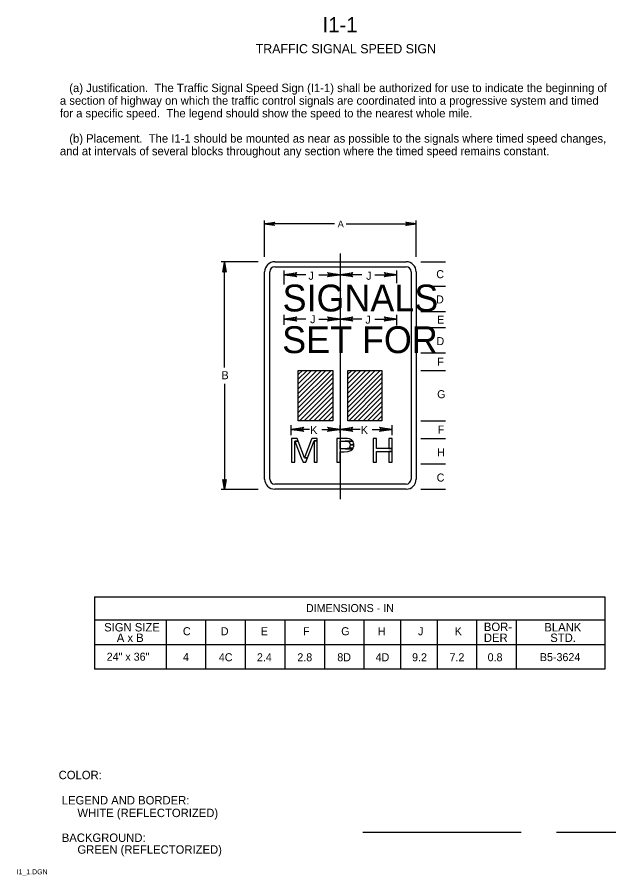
# Model space of a CAD drawing. Extents: x 0.013 to 0.191, y 0.004 to 0.259.
import ezdxf

# ---------------------------------------------------------------- set-up
doc = ezdxf.new("R2010")
doc.units = 0
for name, color, linetype in [('1', 7, 'Continuous'), ('2', 7, 'Continuous'), ('3', 7, 'Continuous')]:
    doc.layers.add(name, color=color, linetype=linetype)

# ---------------------------------------------------------------- blocks, each defined once
blk = doc.blocks.new('RARROW')
at = {"layer": '3'}
blk.add_lwpolyline([(-2.2695, 0.285), (-2.184875, 0.12075), (0, 0), (-2.2695, 0.285), (-2.38575, 0.384625), (0, 0), (-2.183125, -0.108), (-2.262875, -0.2705), (0, 0), (-2.38575, -0.379125), (-2.262875, -0.2705)], dxfattribs=at)

msp = doc.modelspace()

# ---------------------------------------------------------------- linework, layer by layer
at = {"layer": '1'}
for p, q in [((0.08625, 0.18768), (0.08625, 0.1985)), ((0.107, 0.1975), (0.08625, 0.1975)), ((0.1105, 0.1975), (0.13125, 0.1975)), ((0.13125, 0.18768), (0.13125, 0.1985)), ((0.10875, 0.18875), (0.10875, 0.11575)), ((0.08436, 0.18625), (0.07342, 0.18625)), ((0.07437, 0.15488), (0.07437, 0.18625)), ((0.13262, 0.18625), (0.14, 0.18625)), ((0.09212, 0.17955), (0.09212, 0.18365)), ((0.10875, 0.18415), (0.10875, 0.18115)), ((0.1255, 0.17992), (0.1255, 0.18365)), ((0.0985, 0.1824), (0.09212, 0.1824)), ((0.10237, 0.1824), (0.10875, 0.1824)), ((0.11512, 0.1824), (0.10875, 0.1824)), ((0.119, 0.1824), (0.1255, 0.1824)), ((0.13262, 0.179), (0.14, 0.179)), ((0.10875, 0.171), (0.10875, 0.168)), ((0.13262, 0.1715), (0.14, 0.1715)), ((0.09212, 0.1675), (0.09212, 0.1705)), ((0.0985, 0.16925), (0.09212, 0.16925)), ((0.10237, 0.16925), (0.10875, 0.16925)), ((0.11512, 0.16925), (0.10875, 0.16925)), ((0.119, 0.16925), (0.1255, 0.16925)), ((0.1255, 0.16737), (0.1255, 0.1705)), ((0.13262, 0.16675), (0.14, 0.16675)), ((0.13262, 0.15925), (0.14, 0.15925)), ((0.09625, 0.15275), (0.0975, 0.154)), ((0.09625, 0.15138), (0.09888, 0.154)), ((0.09625, 0.15), (0.10025, 0.154)), ((0.09625, 0.1485), (0.10175, 0.154)), ((0.09625, 0.14713), (0.10313, 0.154)), ((0.09625, 0.14575), (0.1045, 0.154)), ((0.09625, 0.14425), (0.106, 0.154)), ((0.09625, 0.14288), (0.1065, 0.15313)), ((0.111, 0.15288), (0.11213, 0.154)), ((0.111, 0.1515), (0.1135, 0.154)), ((0.111, 0.15013), (0.11488, 0.154)), ((0.111, 0.14863), (0.11638, 0.154)), ((0.111, 0.14725), (0.11775, 0.154)), ((0.111, 0.14588), (0.11913, 0.154)), ((0.111, 0.14438), (0.12062, 0.154)), ((0.111, 0.143), (0.12112, 0.15313)), ((0.13262, 0.154), (0.14, 0.154)), ((0.09625, 0.1415), (0.1065, 0.15175)), ((0.111, 0.14163), (0.12112, 0.15175)), ((0.07437, 0.15), (0.07437, 0.11863)), ((0.09625, 0.14012), (0.1065, 0.15038)), ((0.09663, 0.139), (0.1065, 0.14888)), ((0.111, 0.14025), (0.12112, 0.15038)), ((0.11125, 0.139), (0.12112, 0.14888)), ((0.098, 0.139), (0.1065, 0.1475)), ((0.09938, 0.139), (0.1065, 0.14613)), ((0.11263, 0.139), (0.12112, 0.1475)), ((0.114, 0.139), (0.12112, 0.14613)), ((0.10088, 0.139), (0.1065, 0.14463)), ((0.10225, 0.139), (0.1065, 0.14325)), ((0.1155, 0.139), (0.12112, 0.14463)), ((0.11688, 0.139), (0.12112, 0.14325)), ((0.10363, 0.139), (0.1065, 0.14188)), ((0.10512, 0.139), (0.1065, 0.14037)), ((0.11825, 0.139), (0.12112, 0.14188)), ((0.11975, 0.139), (0.12112, 0.14037)), ((0.09413, 0.13475), (0.09413, 0.13775)), ((0.10875, 0.1355), (0.10875, 0.13775)), ((0.12412, 0.13475), (0.12412, 0.13775)), ((0.13262, 0.139), (0.14, 0.139)), ((0.09963, 0.1365), (0.09413, 0.1365)), ((0.10325, 0.1365), (0.10875, 0.1365)), ((0.11463, 0.1365), (0.10875, 0.1365)), ((0.11825, 0.1365), (0.12412, 0.1365)), ((0.13262, 0.13375), (0.14, 0.13375)), ((0.13262, 0.12625), (0.14, 0.12625)), ((0.08438, 0.11865), (0.07343, 0.11865)), ((0.13262, 0.11875), (0.14, 0.11875)), ((0.11544, 0.01695), (0.16242, 0.01695)), ((0.17295, 0.01695), (0.19056, 0.01695))]:
    msp.add_line(p, q, dxfattribs=at)
for points in [[(0.09625, 0.154), (0.1065, 0.154), (0.1065, 0.139), (0.09625, 0.139)], [(0.111, 0.154), (0.12112, 0.154), (0.12112, 0.139), (0.111, 0.139)], [(0.09422, 0.12806), (0.09422, 0.12675), (0.09522, 0.12675), (0.09522, 0.12806), (0.09522, 0.13301), (0.09624, 0.13301), (0.09593, 0.13382), (0.09422, 0.13382), (0.09422, 0.13301)], [(0.09718, 0.12806), (0.0977, 0.12675), (0.09856, 0.12675), (0.09905, 0.12806), (0.09815, 0.12806), (0.09624, 0.13301), (0.09522, 0.13301)], [(0.1, 0.13307), (0.09815, 0.12806), (0.09905, 0.12806), (0.10095, 0.13307), (0.10193, 0.13307), (0.10193, 0.13382), (0.10027, 0.13382)], [(0.10095, 0.12806), (0.10095, 0.12675), (0.10193, 0.12675), (0.10193, 0.12806), (0.10193, 0.13307), (0.10095, 0.13307)], [(0.10774, 0.12986), (0.10774, 0.12675), (0.10874, 0.12675), (0.10874, 0.12986), (0.10986, 0.12986), (0.111, 0.12993), (0.11187, 0.13021), (0.11243, 0.13071), (0.11244, 0.13072), (0.10874, 0.13072), (0.10874, 0.13073), (0.10874, 0.13077), (0.10874, 0.13092), (0.10874, 0.13128), (0.10874, 0.13136), (0.10874, 0.13186), (0.10874, 0.13214), (0.10874, 0.13244), (0.10874, 0.1328), (0.10874, 0.1329), (0.10874, 0.13295), (0.10874, 0.133), (0.10874, 0.13301), (0.11245, 0.13301), (0.11207, 0.13342), (0.11148, 0.13369), (0.11087, 0.13379), (0.11035, 0.13382), (0.10774, 0.13382), (0.10774, 0.13379), (0.10774, 0.13369), (0.10774, 0.13342), (0.10774, 0.13301), (0.10774, 0.133), (0.10774, 0.13295), (0.10774, 0.1329), (0.10774, 0.1328), (0.10774, 0.13244), (0.10774, 0.13214), (0.10774, 0.13186), (0.10774, 0.13136), (0.10774, 0.13128), (0.10774, 0.13092), (0.10774, 0.13077), (0.10774, 0.13073), (0.10774, 0.13072), (0.10774, 0.13071), (0.10774, 0.13021), (0.10774, 0.12993)], [(0.11167, 0.13214), (0.11173, 0.13186), (0.11276, 0.13186), (0.11277, 0.13214), (0.11269, 0.13244), (0.11258, 0.1328), (0.11258, 0.1328), (0.11255, 0.1329), (0.1125, 0.13295), (0.11246, 0.133), (0.11245, 0.13301), (0.11018, 0.13301), (0.11045, 0.133), (0.11088, 0.13295), (0.11102, 0.1329), (0.1113, 0.1328), (0.11161, 0.13244)], [(0.1185, 0.12996), (0.1185, 0.12675), (0.11951, 0.12675), (0.11951, 0.12996), (0.12419, 0.12996), (0.12419, 0.1308), (0.11951, 0.1308), (0.11951, 0.13382), (0.1185, 0.13382), (0.1185, 0.1308)], [(0.12319, 0.13382), (0.12319, 0.1308), (0.12419, 0.1308), (0.12419, 0.13382)], [(0.11041, 0.13073), (0.11018, 0.13072), (0.11244, 0.13072), (0.11244, 0.13073), (0.11246, 0.13077), (0.11253, 0.13092), (0.11127, 0.13092), (0.11082, 0.13077)], [(0.11161, 0.13128), (0.11127, 0.13092), (0.11253, 0.13092), (0.11269, 0.13128), (0.11273, 0.13136), (0.11276, 0.13186), (0.11173, 0.13186), (0.11163, 0.13136)], [(0.12319, 0.12996), (0.12319, 0.12675), (0.12419, 0.12675), (0.12419, 0.12996)]]:
    msp.add_lwpolyline(points, close=True, dxfattribs=at)
at = {"layer": '3'}
for p, q in [((0.08929, 0.18625), (0.12829, 0.18625)), ((0.08929, 0.18475), (0.12829, 0.18475)), ((0.08629, 0.12175), (0.08629, 0.18325)), ((0.08779, 0.12175), (0.08779, 0.18325)), ((0.12979, 0.18325), (0.12979, 0.12175)), ((0.13129, 0.18325), (0.13129, 0.12175)), ((0.12829, 0.12025), (0.08929, 0.12025)), ((0.12829, 0.11875), (0.08929, 0.11875)), ((0.03577, 0.08675), (0.18727, 0.08675)), ((0.03577, 0.08675), (0.03577, 0.06525)), ((0.18727, 0.08675), (0.18727, 0.06525)), ((0.18727, 0.07988), (0.03577, 0.07988)), ((0.05706, 0.0799), (0.05706, 0.06527)), ((0.06877, 0.07988), (0.06877, 0.06525)), ((0.08052, 0.07988), (0.08052, 0.06525)), ((0.09227, 0.07988), (0.09227, 0.06525)), ((0.10402, 0.07988), (0.10402, 0.06525)), ((0.11577, 0.07988), (0.11577, 0.06525)), ((0.12664, 0.07988), (0.12664, 0.06525)), ((0.13752, 0.07988), (0.13752, 0.06525)), ((0.14919, 0.0799), (0.14919, 0.06527)), ((0.16094, 0.0799), (0.16094, 0.06527)), ((0.18727, 0.0725), (0.03577, 0.0725)), ((0.18727, 0.06525), (0.03577, 0.06525))]:
    msp.add_line(p, q, dxfattribs=at)
for centre, radius, start, end in [((0.08929, 0.18325), 0.003, 90, 180), ((0.12829, 0.18325), 0.003, 0, 90), ((0.08929, 0.18325), 0.0015, 90, 180), ((0.12829, 0.18325), 0.0015, 0, 90), ((0.08929, 0.12175), 0.003, 180, 270), ((0.08929, 0.12175), 0.0015, 180, 270), ((0.12829, 0.12175), 0.003, 270, 0), ((0.12829, 0.12175), 0.0015, 270, 0)]:
    msp.add_arc(centre, radius, start, end, dxfattribs=at)

# ---------------------------------------------------------------- block references
at = {"layer": '1'}
for p, xscale, yscale, rotation in [((0.08625, 0.1975), 0.0012574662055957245, 0.001309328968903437, 180), ((0.07437, 0.18613), 0.0012574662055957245, 0.001309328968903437, 90), ((0.09212, 0.1824), 0.0015718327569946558, 0.0016366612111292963, 180), ((0.10875, 0.1824), 0.0015718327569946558, 0.0016366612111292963, 180), ((0.09212, 0.16925), 0.0015718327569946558, 0.0016366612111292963, 180), ((0.10875, 0.16925), 0.0015718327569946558, 0.0016366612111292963, 180), ((0.09413, 0.1365), 0.0015718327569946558, 0.0016366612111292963, 180), ((0.10875, 0.1365), 0.0015718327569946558, 0.0016366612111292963, 180), ((0.07437, 0.11863), 0.0012574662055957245, 0.001309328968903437, -90)]:
    msp.add_blockref('RARROW', p, dxfattribs=dict(at, xscale=xscale, yscale=yscale, rotation=rotation))
for p, xscale, yscale in [((0.13125, 0.1975), 0.0012574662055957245, 0.001309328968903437), ((0.10875, 0.1824), 0.0015718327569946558, 0.0016366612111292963), ((0.1255, 0.1824), 0.0015718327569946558, 0.0016366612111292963), ((0.10875, 0.16925), 0.0015718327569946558, 0.0016366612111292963), ((0.1255, 0.16925), 0.0015718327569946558, 0.0016366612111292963), ((0.10875, 0.1365), 0.0015718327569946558, 0.0016366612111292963), ((0.12412, 0.1365), 0.0015718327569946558, 0.0016366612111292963)]:
    msp.add_blockref('RARROW', p, dxfattribs=dict(at, xscale=xscale, yscale=yscale))

# ---------------------------------------------------------------- texts
for s, height, p in [('I1-1', 0.0045, (0.1035, 0.25438)), ('TRAFFIC SIGNAL SPEED SIGN', 0.0027503, (0.08363, 0.24813)), ('A', 0.002, (0.108, 0.1965)), ('C', 0.00238, (0.13725, 0.18138)), ('J', 0.00238, (0.0993, 0.1809)), ('J', 0.00238, (0.11643, 0.1809)), ('SIGNALS', 0.007972, (0.09162, 0.1715)), ('D', 0.00238, (0.13718, 0.17388)), ('J', 0.00238, (0.0998, 0.168)), ('J', 0.00238, (0.11618, 0.16787)), ('E', 0.00238, (0.1375, 0.16787)), ('SET FOR', 0.007972, (0.0915, 0.15913)), ('D', 0.00238, (0.13731, 0.1615)), ('F', 0.00238, (0.13753, 0.15538)), ('B', 0.00238, (0.0735, 0.15138)), ('G', 0.00238, (0.13752, 0.14575)), ('K', 0.00238, (0.09984, 0.13512)), ('K', 0.00238, (0.11484, 0.13512)), ('F', 0.00238, (0.13766, 0.13525)), ('H', 0.00238, (0.13746, 0.1285)), ('C', 0.00238, (0.13737, 0.121)), ('C', 0.00238, (0.06202, 0.07537)), ('D', 0.00238, (0.07327, 0.07537)), ('E', 0.00238, (0.08515, 0.07537)), ('F', 0.00238, (0.09767, 0.07537)), ('G', 0.00238, (0.10903, 0.07537)), ('H', 0.00238, (0.11985, 0.07537)), ('J', 0.00238, (0.13182, 0.07537)), ('K', 0.00238, (0.14274, 0.07537)), ('24" x 36"', 0.002375, (0.03939, 0.06781)), ('4', 0.00238, (0.06203, 0.06769)), ('4C', 0.002375, (0.07269, 0.06765)), ('2.4', 0.002375, (0.084, 0.06765)), ('2.8', 0.002375, (0.096, 0.06765)), ('8D', 0.002375, (0.10787, 0.06765)), ('4D', 0.002375, (0.11924, 0.06765)), ('9.2', 0.002375, (0.13007, 0.06765)), ('7.2', 0.002375, (0.14119, 0.06765)), ('0.8', 0.002375, (0.1525, 0.06765)), ('B5-3624', 0.002375, (0.16801, 0.06769)), ('I1_1.DGN', 0.0015, (0.01263, 0.00438))]:
    msp.add_text(s, height=height, dxfattribs=at).set_placement(p)
at = {"layer": '2'}
for s, height, p in [('   (a) Justification.  The Traffic Signal Speed Sign (I1-1) shall be authorized for use to indicate the beginning of', 0.00249975, (0.0255, 0.23663)), ('a section of highway on which the traffic control signals are coordinated into a progressive system and timed', 0.00249975, (0.0255, 0.23287)), ('for a specific speed.  The legend should show the speed to the nearest whole mile.', 0.0024998, (0.0255, 0.22912)), ('   (b) Placement.  The I1-1 should be mounted as near as possible to the signals where timed speed changes,', 0.00249975, (0.0255, 0.22163)), ('and at intervals of several blocks throughout any section where the timed speed remains constant.', 0.0024998, (0.0255, 0.21788)), ('COLOR:', 0.0025, (0.02513, 0.03263)), (' LEGEND AND BORDER:', 0.0024998, (0.02513, 0.02513)), ('      WHITE (REFLECTORIZED)', 0.0024998, (0.02513, 0.02138)), (' BACKGROUND:', 0.0024998, (0.02513, 0.014)), ('      GREEN (REFLECTORIZED)', 0.0024998, (0.02513, 0.0105))]:
    msp.add_text(s, height=height, dxfattribs=at).set_placement(p)
at = {"layer": '3'}
for s, height, p in [('DIMENSIONS - IN', 0.0023752, (0.09856, 0.08225)), ('SIGN SIZE', 0.0025, (0.03864, 0.0765)), ('BOR-', 0.0025, (0.15139, 0.07662)), ('BLANK', 0.0025, (0.16935, 0.0765)), ('A x B', 0.0025, (0.04239, 0.07337)), ('DER', 0.0025, (0.15139, 0.07337)), ('STD.', 0.0025, (0.1711, 0.07337))]:
    msp.add_text(s, height=height, dxfattribs=at).set_placement(p)

doc.saveas('drawing.dxf')
